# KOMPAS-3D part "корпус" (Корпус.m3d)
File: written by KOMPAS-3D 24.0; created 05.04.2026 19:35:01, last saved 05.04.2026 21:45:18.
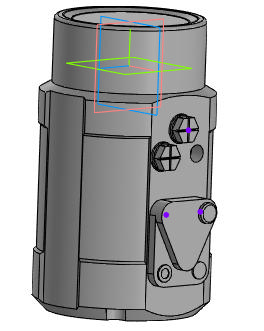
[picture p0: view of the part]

Document properties: Автор: R2D2; Полное имя файла: C:\Users\R2D2\Desktop\ЭИП-1600 Электропневматический позиционер DN.ru — копия\5-25\исходные материалы\Корпус.m3d

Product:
- Part/product: корпус
    Масса: 9.19942
    Раздел спецификации: Прочие изделия
    Примечание: D900-02741

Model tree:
1. Эскиз:1
2. Элемент вращения:1
     Угол 1 = 360
3. Эскиз:2  (with: Грань.Элемент вращения:1)
4. Элемент выдавливания:1
     Расстояние 2 = 139
5. Фаска:2  (with: Ребро.Элемент выдавливания:1)
     Угол = 45; Длина 1 = 4; Длина 2 = 4
6. Массив по концентрической сетке:1  (with: Элемент выдавливания:1, Эскиз:2, Фаска:2, Грань.Элемент вращения:1)  (3 pattern instances)
     Шаг 2 = 90
7. Эскиз:3  (with: Грань.Элемент вращения:1, Ребро.Элемент вращения:1)
8. Элемент выдавливания:2
     Расстояние 2 = 139
9. Эскиз:4  (with: Ребро.Элемент выдавливания:2, Ребро.Элемент вращения:1)
10. Элемент вращения:2
     Угол 1 = 360
11. Скругление:1  (with: Ребро.Элемент вращения:2)
     Радиус = 2
12. Эскиз:5  (with: Грань.Элемент вращения:1)
13. Элемент выдавливания:3
     Расстояние 2 = 7.5
14. Массив по концентрической сетке:2  (with: Элемент выдавливания:3, Эскиз:5)  (4 pattern instances)
     Шаг 2 = 360
15. Эскиз:6  (with: Грань.Элемент выдавливания:2, Ребро.Элемент выдавливания:2, Вершина.Элемент вращения:2)
16. Элемент выдавливания:4
     Расстояние 2 = 10
17. Эскиз:7  (with: Грань.Элемент выдавливания:2)
18. Элемент выдавливания:6
     Расстояние 2 = 10
19. Эскиз:8  (with: Грань.Элемент выдавливания:2, Ребро.Элемент выдавливания:6)
20. Элемент выдавливания:7
     Расстояние 1 = 2
21. Скругление:2  (with: Ребро.Элемент выдавливания:7)
     Радиус = 0.5
22. Эскиз:9  (with: Грань.Элемент выдавливания:7, Ребро.Скругление:2, Ребро.Элемент выдавливания:7)
23. Элемент выдавливания:8
     Расстояние 1 = 5
24. Эскиз:10  (with: Грань.Элемент выдавливания:8, Ребро.Элемент выдавливания:7)
25. Элемент выдавливания:9
     Расстояние 2 = 2
26. Массив по концентрической сетке:3  (with: Элемент выдавливания:9, Грань.Элемент выдавливания:7)  (4 pattern instances)
     Шаг 2 = 360
27. Точка:1  (with: Грань.Элемент выдавливания:8)
     X = 52; Y = -30
28. Массив по точкам:1
29. Экземпляр ( 1 )  (with: Массив по концентрической сетке:3, Элемент выдавливания:9)
30. Экземпляр ( 2 )  (with: Элемент выдавливания:9)
31. Экземпляр ( 3 )  (with: Элемент выдавливания:9)
32. Экземпляр ( 4 )  (with: Элемент выдавливания:9)
33. Эскиз:11  (with: Грань.Элемент выдавливания:2, Ребро.Элемент выдавливания:2, Ребро.Элемент выдавливания:4)
34. Элемент выдавливания:10
     Расстояние 1 = 5
35. Элемент выдавливания:11
     Расстояние 1 = 2
36. Скругление:3  (with: Ребро.Элемент выдавливания:10)
     Радиус = 8
37. Точка:2  (with: Ребро.Скругление:3)
     X = 50; Y = -77.5; Z = -12.7945
38. Точка:3  (with: Ребро.Скругление:3)
     X = 50; Y = -77.5; Z = 12.7945
39. Эскиз:13  (with: Грань.Элемент выдавливания:10, Вершина.Скругление:3, Ребро.Элемент выдавливания:10)
40. Элемент выдавливания:13
     Расстояние 1 = 5
41. Эскиз:14  (with: Грань.Элемент выдавливания:10, Ребро.Элемент выдавливания:10)
42. Элемент выдавливания:14
     Расстояние 1 = 1
43. Эскиз:15  (with: Грань.Элемент выдавливания:14, Ребро.Элемент выдавливания:14)
44. Элемент выдавливания:15
     Расстояние 2 = 0.5
45. Эскиз:16  (with: Грань.Элемент выдавливания:13)
46. Элемент выдавливания:16
     Расстояние 1 = 3
47. Скругление:4  (with: Ребро.Элемент выдавливания:16)
     Радиус = 1
48. Эскиз:17  (with: Грань.Элемент вращения:2)
49. Элемент вращения:3
     Угол 1 = 360

Expressions: 45+22.5
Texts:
  Точка начала. Х
  Точка начала. Y
  Точка начала. Z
